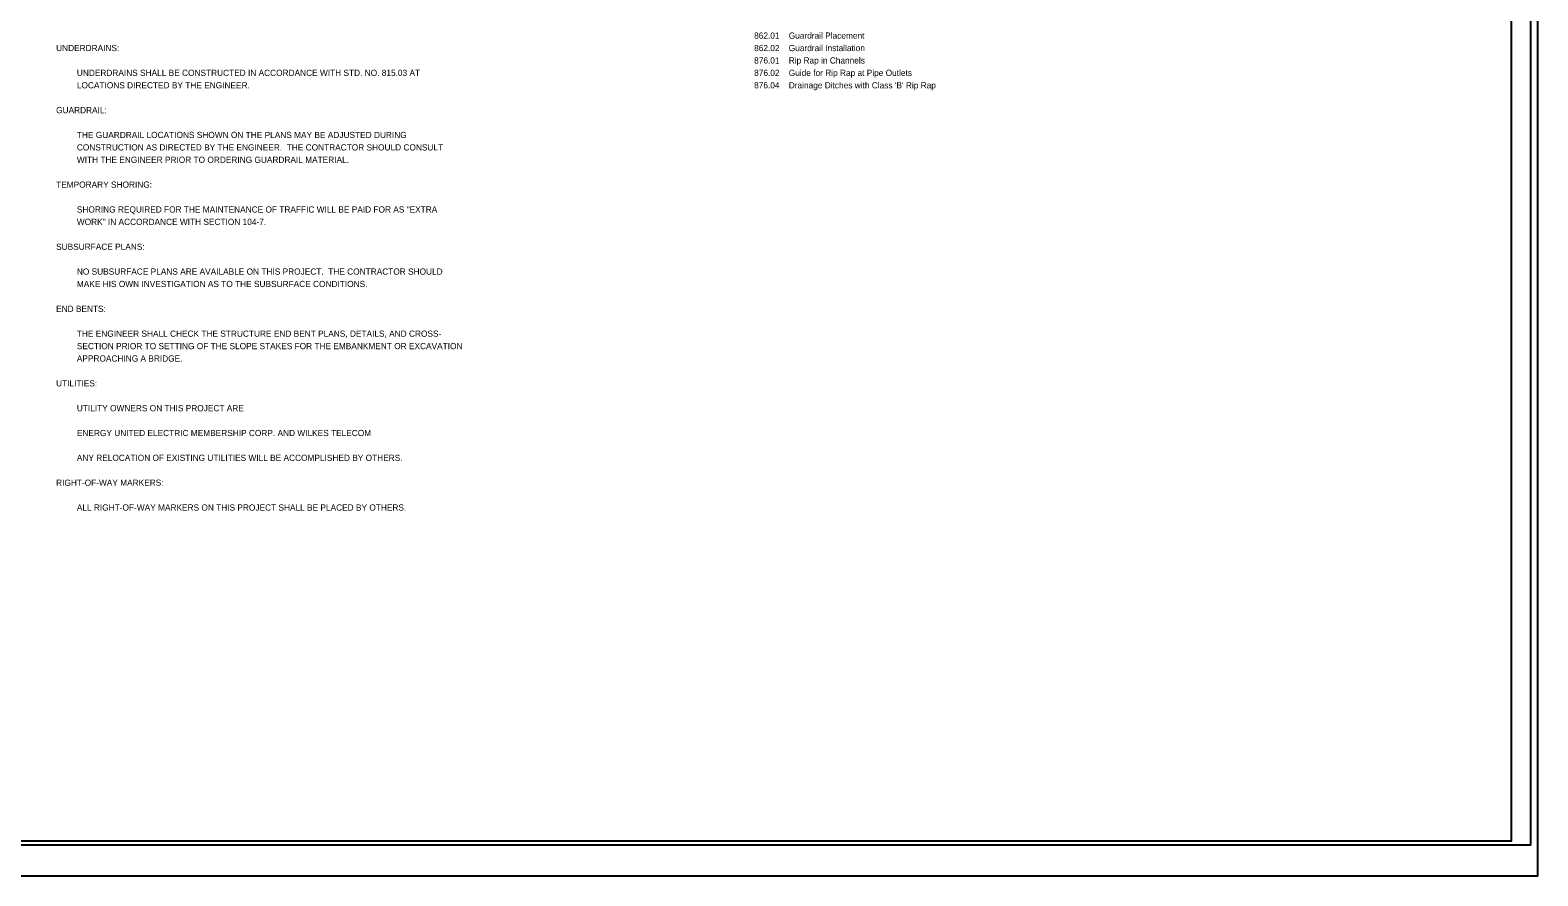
# Model space of a CAD drawing. Extents: x 573606 to 575290, y -53273 to -52178.
# Drawn here: x 574319 to 575290, y -53273 to -52728 of the extents above; entities that cross this region are included whole.
import ezdxf

# ---------------------------------------------------------------- set-up
doc = ezdxf.new("R2010")
doc.units = 0
for name, color, linetype in [('Default', 7, 'Continuous'), ('Sheet Cutting Line CELL', 7, 'Continuous'), ('Sheet Plan CELL', 7, 'Continuous'), ('Sheet Plot Border Inside CELL', 7, 'Continuous'), ('Sheet Plot Border Outside CELL', 7, 'Continuous')]:
    doc.layers.add(name, color=color, linetype=linetype)

msp = doc.modelspace()

# ---------------------------------------------------------------- linework, layer by layer
at = {"layer": 'Sheet Cutting Line CELL'}
msp.add_line((573606.46, -53272.62), (575289.96, -53272.62), dxfattribs=at)
at = {"layer": 'Sheet Plan CELL'}
msp.add_lwpolyline([(575272.96, -52200.12), (573772.96, -52200.12), (573772.96, -53250.12), (575272.96, -53250.12)], close=True, dxfattribs=at)
at = {"layer": 'Sheet Plot Border Inside CELL'}
msp.add_lwpolyline([(573619.46, -53252.62), (575285.46, -53252.62), (575285.46, -52197.62), (573619.46, -52197.62)], close=True, dxfattribs=at)
at = {"layer": 'Sheet Plot Border Outside CELL'}
msp.add_lwpolyline([(573606.46, -53272.62), (575289.96, -53272.62), (575289.96, -52177.62), (573606.46, -52177.62)], close=True, dxfattribs=at)

# ---------------------------------------------------------------- texts
at = {"layer": 'Default'}
for s, p in [('862.01    Guardrail Placement', (574785.02, -52733.36)), ('UNDERDRAINS:  ', (574335.28, -52741.36)), ('862.02    Guardrail Installation', (574785.02, -52741.36)), ('876.01    Rip Rap in Channels', (574785.02, -52749.36)), ('         UNDERDRAINS SHALL BE CONSTRUCTED IN ACCORDANCE WITH STD. NO. 815.03 AT ', (574335.28, -52757.36)), ('876.02    Guide for Rip Rap at Pipe Outlets', (574785.02, -52757.36)), ('         LOCATIONS DIRECTED BY THE ENGINEER.  ', (574335.28, -52765.36)), ("876.04    Drainage Ditches with Class 'B' Rip Rap", (574785.02, -52765.36)), ('GUARDRAIL:  ', (574335.28, -52781.36)), ('         THE GUARDRAIL LOCATIONS SHOWN ON THE PLANS MAY BE ADJUSTED DURING ', (574335.28, -52797.36)), ('         CONSTRUCTION AS DIRECTED BY THE ENGINEER.  THE CONTRACTOR SHOULD CONSULT', (574335.28, -52805.36)), ('         WITH THE ENGINEER PRIOR TO ORDERING GUARDRAIL MATERIAL.', (574335.28, -52813.36)), ('TEMPORARY SHORING:  ', (574335.28, -52829.36)), ('         SHORING REQUIRED FOR THE MAINTENANCE OF TRAFFIC WILL BE PAID FOR AS "EXTRA ', (574335.28, -52845.36)), ('         WORK" IN ACCORDANCE WITH SECTION 104-7.  ', (574335.28, -52853.36)), ('SUBSURFACE PLANS:  ', (574335.28, -52869.36)), ('         NO SUBSURFACE PLANS ARE AVAILABLE ON THIS PROJECT.  THE CONTRACTOR SHOULD ', (574335.28, -52885.36)), ('         MAKE HIS OWN INVESTIGATION AS TO THE SUBSURFACE CONDITIONS.  ', (574335.28, -52893.36)), ('END BENTS:  ', (574335.28, -52909.36)), ('         THE ENGINEER SHALL CHECK THE STRUCTURE END BENT PLANS, DETAILS, AND CROSS-', (574335.28, -52925.36)), ('         SECTION PRIOR TO SETTING OF THE SLOPE STAKES FOR THE EMBANKMENT OR EXCAVATION ', (574335.28, -52933.36)), ('         APPROACHING A BRIDGE.  ', (574335.28, -52941.36)), ('UTILITIES:  ', (574335.28, -52957.36)), ('         UTILITY OWNERS ON THIS PROJECT ARE  ', (574335.28, -52973.36)), ('         ENERGY UNITED ELECTRIC MEMBERSHIP CORP. AND WILKES TELECOM', (574335.28, -52989.36)), ('         ANY RELOCATION OF EXISTING UTILITIES WILL BE ACCOMPLISHED BY OTHERS.  ', (574335.28, -53005.36)), ('RIGHT-OF-WAY MARKERS:  ', (574335.28, -53021.36)), ('         ALL RIGHT-OF-WAY MARKERS ON THIS PROJECT SHALL BE PLACED BY OTHERS.  ', (574335.28, -53037.36))]:
    msp.add_text(s, height=4, dxfattribs=at).set_placement(p)

doc.saveas('drawing.dxf')
